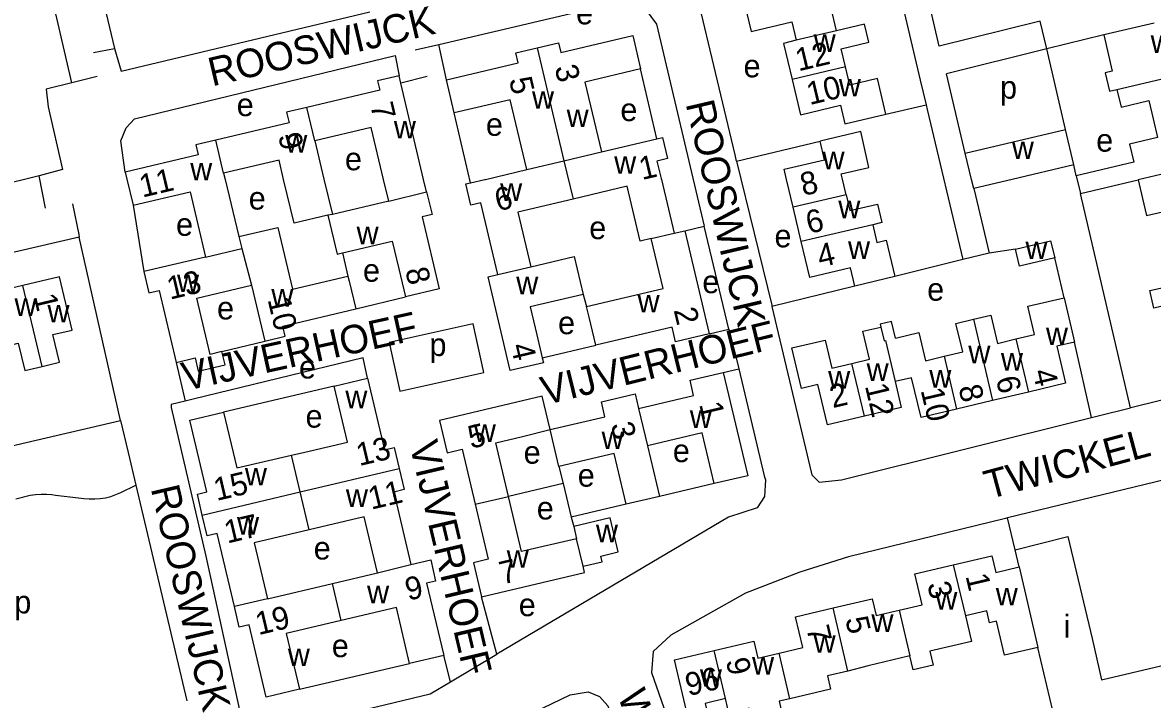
# Model space of a CAD drawing. Extents: x 157646 to 159241, y 379213 to 381217.
# Drawn here: x 158162.1 to 158360.1, y 380658.9 to 380777.5 of the extents above; entities that cross this region are included whole.
import ezdxf

# ---------------------------------------------------------------- set-up
doc = ezdxf.new("R2010")
doc.units = 0
for name, color, linetype in [('BLT_Basislijn', 7, 'Continuous'), ('BLT_Bebouwing', 7, 'Continuous'), ('BLT_Centroide', 7, 'Continuous'), ('BLT_Huisnummer', 7, 'Continuous'), ('BLT_Huisnummer_ tussenligend', 7, 'Continuous'), ('BLT_Onderverdeling_panden', 7, 'Continuous'), ('BLT_Straatnaam', 7, 'Continuous')]:
    doc.layers.add(name, color=color, linetype=linetype)

msp = doc.modelspace()

# ---------------------------------------------------------------- linework, layer by layer
at = {"layer": 'BLT_Basislijn'}
for p, q in [((158316.59, 380779.32), (158319.36, 380767.4)), ((158351.53, 380775.34), (158341.59, 380772.88)), ((158174.55, 380772.25), (158178.24, 380772.97)), ((158230.92, 380772.74), (158235.05, 380773.67)), ((158236.36, 380767.45), (158235.05, 380773.67)), ((158341.59, 380772.88), (158323.97, 380768.54)), ((158344.81, 380758.77), (158341.59, 380772.88)), ((158273.22, 380757.15), (158270.38, 380769.39)), ((158327.27, 380754.62), (158323.97, 380768.54)), ((158175.2, 380768.03), (158170.71, 380766.93)), ((158232.99, 380768.03), (158228.38, 380766.87)), ((158319.36, 380767.4), (158320.4, 380763.12)), ((158313.37, 380761.48), (158320.4, 380763.12)), ((158240.57, 380749.4), (158237.73, 380761.67)), ((158287.22, 380753.19), (158301.83, 380756.71)), ((158346.72, 380750.66), (158346.28, 380752.55)), ((158165, 380750.66), (158156.46, 380748.53)), ((158166.1, 380744.95), (158165, 380750.66)), ((158328.77, 380748.41), (158331.46, 380737.09)), ((158356.21, 380709.98), (158347.45, 380747.57)), ((158181.5, 380745.49), (158183.37, 380733.86)), ((158278.13, 380741.02), (158281.54, 380741.81)), ((158285.84, 380723.75), (158281.54, 380741.81)), ((158179.27, 380707.73), (158172.05, 380739.92)), ((158331.46, 380737.09), (158326.85, 380735.95)), ((158336.08, 380737.81), (158331.46, 380737.09)), ((158326.85, 380735.95), (158314.92, 380732.98)), ((158344.58, 380729.27), (158342.94, 380736.24)), ((158307.9, 380731.31), (158293.41, 380727.76)), ((158220.47, 380727.33), (158229.18, 380729.46)), ((158260.33, 380729.87), (158260.92, 380727.74)), ((158282.41, 380722.92), (158285.84, 380723.75)), ((158197.04, 380719.84), (158204.54, 380721.68)), ((158253.15, 380718.76), (158262.52, 380720.97)), ((158349.37, 380708.3), (158346.42, 380721.5)), ((158189.03, 380717.94), (158190.58, 380711.16)), ((158284.88, 380716.18), (158287.6, 380716.79)), ((158216.71, 380713.78), (158197.33, 380709.22)), ((158179.27, 380707.73), (158180.59, 380702.15)), ((158180.59, 380702.15), (158181.94, 380696.44)), ((158256.06, 380699.67), (158256.8, 380696.68)), ((158179.3, 380695.11), (158181.94, 380696.44)), ((158256.8, 380696.68), (158247.24, 380694.45)), ((158256.8, 380696.68), (158258.24, 380690.82)), ((158283.3, 380696.69), (158273.71, 380694.45)), ((158160.93, 380693.99), (158163.43, 380694.64)), ((158167.9, 380694.64), (158171.92, 380694.19)), ((158171.92, 380694.19), (158172.84, 380694.09)), ((158267.87, 380693.07), (158258.24, 380690.82)), ((158258.24, 380690.82), (158258.67, 380689.17)), ((158336.03, 380685.07), (158334.69, 380690.66)), ((158245.23, 380666.76), (158242.49, 380676.85)), ((158237.07, 380661.95), (158235.89, 380666.54)), ((158237.07, 380661.95), (158245.23, 380666.76)), ((158210.61, 380660.64), (158229.92, 380665.13))]:
    msp.add_line(p, q, dxfattribs=at)
for points in [[(158170.71, 380766.93), (158157.33, 380824.72), (158143.35, 380821.29)], [(158287.22, 380753.19), (158286.95, 380754.31), (158276.95, 380796.21)], [(158322.72, 380773.38), (158318.74, 380790.56), (158317.53, 380790.94), (158310.03, 380789.16)], [(158235.05, 380773.67), (158264.14, 380780.52), (158268.46, 380780.84), (158270.28, 380780.5), (158271.2, 380779.95), (158273.15, 380777.26), (158281.54, 380741.81)], [(158176.77, 380779.09), (158178.24, 380772.97)], [(158178.24, 380772.97), (158179.37, 380768.98), (158222.97, 380779.39)], [(158341.59, 380772.88), (158340.39, 380777.74), (158322.72, 380773.38)], [(158180.11, 380751.3), (158179.33, 380756.79), (158180.24, 380759.03), (158181.71, 380760.64), (158227.39, 380771.72), (158228.07, 380768.18)], [(158170.71, 380766.93), (158166.24, 380765.83), (158166.58, 380762.76), (158169.09, 380751.74), (158165, 380750.66)], [(158320.4, 380763.12), (158320.6, 380762.29), (158326.85, 380735.95)], [(158287.22, 380753.19), (158293.36, 380727.96), (158293.41, 380727.76)], [(158170.84, 380745.75), (158171.95, 380740.37), (158172.05, 380739.92)], [(158172.05, 380739.92), (158132.97, 380730.81), (158132.92, 380729.89), (158135.23, 380719.77)], [(158293.41, 380727.76), (158300.42, 380698.25), (158301.7, 380696.94), (158305.6, 380697.36), (158349.37, 380708.3)], [(158241.04, 380724.68), (158226.31, 380721.42), (158228.19, 380712.92), (158242.92, 380716.18), (158241.04, 380724.68)], [(158285.84, 380723.75), (158287.58, 380716.89), (158287.6, 380716.79)], [(158388.71, 380719.25), (158387.04, 380717.55), (158356.52, 380710.05), (158356.21, 380709.98)], [(158222.55, 380715.16), (158221.78, 380718.74), (158191.97, 380711.48), (158190.58, 380711.16)], [(158287.6, 380716.79), (158292.04, 380698.06), (158292.26, 380697.35), (158292.11, 380694.4), (158290.81, 380692.46), (158285.78, 380690.8), (158245.23, 380666.76)], [(158190.58, 380711.16), (158188.15, 380710.58), (158188.12, 380710.02), (158194.21, 380683.94), (158200.09, 380656.96), (158200.56, 380655.7), (158202.03, 380653.89), (158203.87, 380653.16), (158205.21, 380653.16), (158214.6, 380655.3), (158233.53, 380659.84), (158237.07, 380661.95)], [(158349.37, 380708.3), (158350.34, 380708.54), (158356.21, 380709.98)], [(158140.24, 380698.65), (158140.88, 380698.8), (158179.27, 380707.73)], [(158392.15, 380700.09), (158389.9, 380703.01), (158386.52, 380703.27), (158334.69, 380690.66)], [(158172.84, 380694.09), (158173.79, 380694), (158174.74, 380693.99), (158175.69, 380694.06), (158176.63, 380694.21), (158177.56, 380694.44), (158178.46, 380694.75), (158179.3, 380695.11)], [(158181.94, 380696.44), (158190.9, 380658.59)], [(158163.43, 380694.64), (158164.38, 380694.79), (158165.34, 380694.86), (158166.3, 380694.85), (158167.26, 380694.75), (158167.9, 380694.64)], [(158334.69, 380690.66), (158334.32, 380690.56), (158306.8, 380683.88), (158298.28, 380681.17), (158288.74, 380677.5), (158275.69, 380670.09), (158272.57, 380667.25), (158272.32, 380663.58), (158281.74, 380636.45), (158287.85, 380610.84), (158289.05, 380609.24)], [(158181.13, 380636.75), (158239.35, 380650.66), (158258.03, 380659.68), (158261.21, 380660.16), (158263.18, 380659.36), (158264.65, 380657.71), (158273.4, 380632.41), (158278.36, 380611.6), (158277.92, 380608.61), (158276.33, 380607.24), (158272.8, 380606.31), (158209.74, 380591.54), (158208.41, 380590.08)]]:
    msp.add_lwpolyline(points, dxfattribs=at)
at = {"layer": 'BLT_Bebouwing'}
for p, q in [((158360.36, 380777.43), (158351.53, 380775.34)), ((158228.38, 380766.87), (158228.07, 380768.18)), ((158237.73, 380761.67), (158236.36, 380767.45)), ((158296.92, 380767.52), (158298.38, 380761.35)), ((158346.28, 380752.55), (158344.81, 380758.77)), ((158263.52, 380754.85), (158273.22, 380757.15)), ((158346.72, 380750.66), (158347.45, 380747.57)), ((158347.45, 380747.57), (158357.54, 380749.95)), ((158226.27, 380746.22), (158216.4, 380743.88)), ((158298.55, 380739.15), (158297.12, 380745.15)), ((158216.4, 380743.88), (158215.6, 380743.72)), ((158276.3, 380740.59), (158278.13, 380741.02)), ((158278.13, 380741.02), (158282.41, 380722.92)), ((158200.01, 380739.98), (158200.54, 380737.92)), ((158200.54, 380737.92), (158202.22, 380731.47)), ((158218.15, 380737.15), (158219.11, 380733.08)), ((158194.15, 380736.41), (158183.37, 380733.86)), ((158314.92, 380732.98), (158307.9, 380731.31)), ((158162.14, 380731.41), (158155.86, 380729.9)), ((158202.22, 380731.47), (158204.54, 380721.68)), ((158344.58, 380729.27), (158346.42, 380721.5)), ((158216.71, 380713.78), (158222.55, 380715.16)), ((158317.88, 380715.25), (158314.98, 380714.57)), ((158332.05, 380711.25), (158325.75, 380709.76)), ((158338.36, 380712.74), (158332.05, 380711.25)), ((158256.06, 380699.67), (158254.54, 380706.15)), ((158271.61, 380703.33), (158273.71, 380694.45)), ((158273.71, 380694.45), (158267.87, 380693.07)), ((158336.73, 380682.08), (158336.03, 380685.07)), ((158216.42, 380679.19), (158224.27, 380681.04)), ((158205, 380676.49), (158216.42, 380679.19)), ((158235.89, 380666.54), (158229.92, 380665.13))]:
    msp.add_line(p, q, dxfattribs=at)
for points in [[(158304.72, 380776.07), (158303.3, 380782.1), (158298.39, 380780.93), (158297.65, 380784.06)], [(158288.38, 380781.86), (158289.78, 380775.93), (158296.9, 380777.62), (158297.66, 380774.4)], [(158306.28, 380769.74), (158305.53, 380772.92), (158310.36, 380774.06), (158309.61, 380777.23), (158304.72, 380776.07)], [(158252.28, 380773.06), (158256.01, 380773.95), (158256.41, 380772.25), (158269, 380775.24), (158270.38, 380769.39)], [(158297.66, 380774.4), (158295.41, 380773.87), (158296.92, 380767.52)], [(158351.53, 380775.34), (158353.03, 380768.99), (158351.81, 380768.7), (158352.57, 380765.49), (158353.83, 380765.79)], [(158236.36, 380767.45), (158248.96, 380770.44), (158248.55, 380772.18), (158252.28, 380773.06)], [(158270.38, 380769.39), (158260.63, 380767.07), (158263.52, 380754.85)], [(158313.37, 380761.48), (158311.9, 380767.71), (158307.03, 380766.56), (158306.28, 380769.74)], [(158228.07, 380768.18), (158224.32, 380767.29), (158224.7, 380765.68), (158211.93, 380762.65)], [(158232.9, 380747.84), (158232.38, 380750), (158228.38, 380766.87)], [(158353.83, 380765.79), (158354.56, 380762.69), (158359.44, 380763.85), (158360.21, 380760.61)], [(158211.93, 380762.65), (158208.36, 380761.8), (158208.8, 380759.96), (158195.94, 380756.91)], [(158250.44, 380751.74), (158247.53, 380763.99), (158237.73, 380761.67)], [(158298.38, 380761.35), (158305.43, 380763.02), (158306.2, 380759.78), (158313.37, 380761.48)], [(158360.21, 380760.61), (158360.97, 380757.38), (158356.06, 380756.22), (158356.81, 380753.04), (158346.72, 380750.66)], [(158226.27, 380746.22), (158225.34, 380750.01), (158223.18, 380759.12), (158213.31, 380756.78)], [(158306.4, 380747.3), (158305.75, 380750.07), (158305.54, 380750.98), (158310.4, 380752.13), (158308.98, 380758.4), (158301.83, 380756.71)], [(158327.27, 380754.62), (158344.81, 380758.77)], [(158195.94, 380756.91), (158192.48, 380756.09), (158192.9, 380754.33), (158180.11, 380751.3)], [(158213.31, 380756.78), (158214.91, 380750.05), (158216.4, 380743.88)], [(158273.22, 380757.15), (158274.22, 380757.38), (158275.1, 380753.68), (158273.26, 380753.24), (158273.98, 380750.2), (158274.03, 380750), (158276.3, 380740.59)], [(158297.12, 380745.15), (158295.97, 380750), (158295.54, 380751.8), (158302.59, 380753.47), (158301.83, 380756.71)], [(158328.77, 380748.41), (158328.36, 380750), (158327.27, 380754.62)], [(158215.6, 380743.72), (158209.7, 380742.32), (158207.85, 380750), (158207.04, 380753.4), (158197.32, 380751.1)], [(158346.28, 380752.55), (158335.5, 380750), (158328.77, 380748.41)], [(158180.11, 380751.3), (158180.4, 380750.08), (158181.5, 380745.49)], [(158197.32, 380751.1), (158197.58, 380750), (158200.01, 380739.98)], [(158240.57, 380749.4), (158243.12, 380750), (158243.22, 380750.03), (158250.44, 380751.74)], [(158245.38, 380733.34), (158242.41, 380745.92), (158240.67, 380745.5), (158239.79, 380749.22), (158240.57, 380749.4)], [(158272.26, 380739.64), (158270.33, 380739.18), (158268.06, 380748.81), (158258.56, 380746.57)], [(158357.54, 380749.95), (158358.31, 380746.68), (158359.02, 380743.68), (158363.86, 380744.82), (158364.61, 380741.62)], [(158181.5, 380745.49), (158191.45, 380747.84), (158194.15, 380736.41)], [(158232.9, 380747.84), (158233.87, 380743.88), (158232.1, 380743.46), (158235.08, 380730.85), (158229.18, 380729.46)], [(158258.56, 380746.57), (158248.9, 380744.29), (158251.17, 380734.71)], [(158306.4, 380747.3), (158307.04, 380744.54), (158311.9, 380745.7), (158312.67, 380742.46), (158311.05, 380742.08)], [(158215.6, 380743.72), (158217.21, 380736.93), (158218.15, 380737.15)], [(158200.01, 380739.98), (158206.84, 380741.59), (158209.39, 380730.78), (158219.11, 380733.08)], [(158311.05, 380742.08), (158311.8, 380738.95), (158313.41, 380739.34), (158314.92, 380732.98)], [(158218.15, 380737.15), (158226.87, 380739.21), (158228.03, 380734.32), (158229.18, 380729.46)], [(158260.92, 380727.74), (158274.32, 380730.9), (158272.26, 380739.64)], [(158307.9, 380731.31), (158307.15, 380734.5), (158300.06, 380732.81), (158298.55, 380739.15)], [(158336.08, 380737.81), (158342.23, 380739.27), (158342.94, 380736.24)], [(158342.94, 380736.24), (158336.79, 380734.8), (158336.08, 380737.81)], [(158251.17, 380734.71), (158258.77, 380736.51), (158260.33, 380729.87)], [(158165.54, 380717.22), (158168.59, 380717.95), (158167.43, 380722.8), (158170.81, 380723.61), (158168.57, 380732.95), (158162.14, 380731.41)], [(158183.37, 380733.86), (158184.25, 380730.11), (158186.05, 380730.53), (158189.03, 380717.94)], [(158219.11, 380733.08), (158219.32, 380732.19), (158220.47, 380727.33)], [(158253.15, 380718.76), (158253.35, 380717.89), (158247.54, 380716.52), (158243.66, 380732.93), (158245.38, 380733.34)], [(158197.04, 380719.84), (158194.98, 380719.34), (158192.65, 380729.21), (158202.22, 380731.47)], [(158364.52, 380725.01), (158363.76, 380728.25), (158360.33, 380727.44), (158359.6, 380730.53), (158362, 380731.09)], [(158260.33, 380729.87), (158251.04, 380727.67), (158252.2, 380722.76), (158253.15, 380718.76)], [(158336.16, 380722.04), (158339.41, 380722.81), (158338.24, 380727.77), (158344.58, 380729.27)], [(158204.54, 380721.68), (158208.1, 380722.52), (158207.68, 380724.3), (158220.47, 380727.33)], [(158262.52, 380720.97), (158261.37, 380725.84), (158260.92, 380727.74)], [(158315.06, 380722.19), (158314.37, 380725.1), (158312.38, 380724.63), (158312.5, 380724.14)], [(158323.56, 380719.01), (158326.82, 380719.78), (158325.64, 380724.77), (158328.69, 380725.49)], [(158328.69, 380725.49), (158331.74, 380726.21), (158332.9, 380721.27), (158336.16, 380722.04)], [(158282.41, 380722.92), (158276.52, 380721.53), (158275.91, 380724.14), (158262.52, 380720.97)], [(158307.41, 380717.76), (158310.49, 380718.49), (158309.33, 380723.39), (158312.5, 380724.14)], [(158315.06, 380722.19), (158319.15, 380723.15), (158320.31, 380718.24), (158323.56, 380719.01)], [(158158.11, 380720.52), (158161.34, 380721.29), (158162.5, 380716.49), (158165.54, 380717.22)], [(158309.59, 380708.52), (158303.14, 380707), (158301.46, 380714.09), (158298.59, 380713.35), (158296.91, 380720.49), (158302.74, 380721.86), (158303.9, 380716.93), (158307.41, 380717.76)], [(158346.42, 380721.5), (158343.32, 380720.77), (158344.86, 380714.27), (158338.36, 380712.74)], [(158189.03, 380717.94), (158192.32, 380718.72), (158192.87, 380716.38), (158197.59, 380717.5), (158197.04, 380719.84)], [(158222.55, 380715.16), (158225.52, 380702.59), (158227.21, 380702.99), (158228.08, 380699.33)], [(158270.02, 380709.87), (158279.68, 380712.15), (158279.05, 380714.81), (158284.88, 380716.18)], [(158284.88, 380716.18), (158289.16, 380698.08), (158283.3, 380696.69)], [(158325.75, 380709.76), (158319.53, 380708.29), (158317.88, 380715.25)], [(158209.23, 380701.68), (158211.57, 380702.22), (158219.02, 380703.98), (158216.71, 380713.78)], [(158314.98, 380714.57), (158316.04, 380710.04), (158309.59, 380708.52)], [(158254.54, 380706.15), (158253.15, 380712.01), (158235.15, 380707.76), (158236.49, 380702.08), (158239.13, 380702.71), (158241.41, 380693.07)], [(158254.54, 380706.15), (158264.15, 380708.42), (158263.53, 380711.05), (158269.41, 380712.43), (158270.02, 380709.87)], [(158193.6, 380691.18), (158192.73, 380694.86), (158194.37, 380695.24), (158191.39, 380707.82), (158197.33, 380709.22)], [(158197.33, 380709.22), (158199.64, 380699.43), (158209.23, 380701.68)], [(158247.24, 380694.45), (158245.02, 380703.85), (158249.68, 380704.95), (158254.54, 380706.15)], [(158283.3, 380696.69), (158281.2, 380705.6), (158271.61, 380703.33)], [(158267.87, 380693.07), (158265.77, 380701.97), (158256.06, 380699.67)], [(158228.08, 380699.33), (158228.96, 380695.63), (158227.13, 380695.19), (158230.13, 380682.49)], [(158241.41, 380693.07), (158243.69, 380683.43), (158241.09, 380682.81), (158242.49, 380676.85)], [(158259.17, 380687.03), (158249.53, 380684.76), (158247.24, 380694.45)], [(158199.22, 380675.12), (158196.19, 380687.92), (158194.47, 380687.51), (158193.6, 380691.18)], [(158224.27, 380681.04), (158221.95, 380690.89), (158212.31, 380688.61)], [(158260.32, 380682.21), (158263.65, 380682.99), (158263.42, 380683.98), (158266.45, 380684.7), (158265.04, 380690.67), (158258.67, 380689.17)], [(158258.67, 380689.17), (158259.17, 380687.03)], [(158212.31, 380688.61), (158202.68, 380686.33), (158205, 380676.49)], [(158336.03, 380685.07), (158345.27, 380687.41), (158349.48, 380669.51), (158351.17, 380662.3), (158371.95, 380667.18), (158369.16, 380679.07), (158377.01, 380680.91)], [(158230.13, 380682.49), (158233.61, 380683.31), (158234.48, 380679.61), (158232.89, 380679.23), (158235.89, 380666.54)], [(158325.18, 380682.45), (158331.93, 380684.03), (158332.61, 380681.11), (158336.73, 380682.08)], [(158242.49, 380676.85), (158260.57, 380681.12), (158260.32, 380682.21)], [(158315.67, 380674.5), (158319.71, 380675.45), (158318.44, 380680.86), (158325.18, 380682.45)], [(158304.1, 380674.89), (158310.95, 380676.49), (158311.64, 380673.55), (158315.67, 380674.5)], [(158210.61, 380660.64), (158204.81, 380659.27), (158201.82, 380671.94), (158200.07, 380671.53), (158199.22, 380675.12)], [(158229.92, 380665.13), (158227.6, 380674.98), (158217.95, 380672.7)], [(158294.68, 380666.97), (158298.79, 380667.93), (158297.52, 380673.34), (158304.1, 380674.89)], [(158327.29, 380673.5), (158328.34, 380669), (158321.08, 380667.3), (158321.65, 380664.85), (158318.14, 380664.02), (158317.56, 380666.47)], [(158339.99, 380667.96), (158334.14, 380666.59), (158332.74, 380672.55), (158331.52, 380672.26), (158331.03, 380674.38), (158327.29, 380673.5)], [(158217.95, 380672.7), (158208.3, 380670.42), (158210.61, 380660.64)], [(158285.27, 380659), (158281.7, 380658.16), (158282.29, 380655.66), (158278.88, 380654.86), (158276.31, 380665.8), (158283.28, 380667.44)], [(158283.28, 380667.44), (158290.21, 380669.06), (158290.91, 380666.09), (158294.68, 380666.97)], [(158343.74, 380651.99), (158342.6, 380656.85), (158339.99, 380667.96)], [(158317.56, 380666.47), (158310.25, 380664.75), (158306.71, 380663.8)], [(158306.71, 380663.8), (158303.13, 380663), (158303.68, 380660.65), (158296.55, 380658.98)], [(158296.55, 380658.98), (158294.66, 380658.54), (158295.13, 380656.52), (158294.9, 380655.12), (158294.05, 380654.22), (158292.32, 380653.81), (158290.93, 380654.04), (158289.99, 380654.92), (158289.43, 380657.31), (158285.86, 380656.47), (158285.27, 380659)]]:
    msp.add_lwpolyline(points, dxfattribs=at)
at = {"layer": 'BLT_Onderverdeling_panden'}
for p, q in [((158304.72, 380776.07), (158297.66, 380774.4)), ((158252.28, 380773.06), (158256.96, 380753.29)), ((158306.28, 380769.74), (158296.92, 380767.52)), ((158353.83, 380765.79), (158367.95, 380769.13)), ((158213.31, 380756.78), (158211.93, 380762.65)), ((158197.32, 380751.1), (158195.94, 380756.91)), ((158256.96, 380753.29), (158263.52, 380754.85)), ((158250.44, 380751.74), (158256.96, 380753.29)), ((158256.96, 380753.29), (158258.56, 380746.57)), ((158364.64, 380751.63), (158357.54, 380749.95)), ((158226.27, 380746.22), (158232.9, 380747.84)), ((158306.4, 380747.3), (158297.12, 380745.15)), ((158272.26, 380739.64), (158276.3, 380740.59)), ((158311.05, 380742.08), (158298.55, 380739.15)), ((158194.15, 380736.41), (158200.54, 380737.92)), ((158245.38, 380733.34), (158251.17, 380734.71)), ((158165.54, 380717.22), (158162.14, 380731.41)), ((158328.69, 380725.49), (158332.05, 380711.25)), ((158336.16, 380722.04), (158338.36, 380712.74)), ((158323.56, 380719.01), (158325.75, 380709.76)), ((158309.59, 380708.52), (158307.41, 380717.76)), ((158270.02, 380709.87), (158271.61, 380703.33)), ((158210.75, 380695.24), (158209.23, 380701.68)), ((158210.75, 380695.24), (158228.08, 380699.33)), ((158193.6, 380691.18), (158210.75, 380695.24)), ((158212.31, 380688.61), (158210.75, 380695.24)), ((158241.41, 380693.07), (158247.24, 380694.45)), ((158260.32, 380682.21), (158259.17, 380687.03)), ((158224.27, 380681.04), (158230.13, 380682.49)), ((158325.18, 380682.45), (158327.29, 380673.5)), ((158336.73, 380682.08), (158339.99, 380667.96)), ((158217.95, 380672.7), (158216.42, 380679.19)), ((158205, 380676.49), (158199.22, 380675.12)), ((158306.71, 380663.8), (158304.1, 380674.89)), ((158315.67, 380674.5), (158317.56, 380666.47)), ((158285.27, 380659), (158283.28, 380667.44)), ((158296.55, 380658.98), (158294.68, 380666.97))]:
    msp.add_line(p, q, dxfattribs=at)
msp.add_lwpolyline([(158312.5, 380724.14), (158313.07, 380721.72), (158313.27, 380721.77), (158314.98, 380714.57)], dxfattribs=at)

# ---------------------------------------------------------------- texts
at = {"layer": 'BLT_Centroide'}
for s, p in [('e', (158259.09, 380777.2)), ('w', (158300.71, 380772.38)), ('w', (158359.76, 380772.19)), ('e', (158288.43, 380767.91)), ('w', (158305.12, 380764.56)), ('p', (158333.37, 380764.17)), ('w', (158251.36, 380762.41)), ('e', (158199.63, 380761.11)), ('e', (158266.85, 380760.24)), ('e', (158243.29, 380757.66)), ('w', (158257.43, 380759.2)), ('w', (158227.16, 380757.19)), ('w', (158208.13, 380754.72)), ('w', (158335.44, 380753.59)), ('e', (158350.21, 380754.88)), ('e', (158218.59, 380751.62)), ('w', (158302.26, 380751.78)), ('w', (158191.48, 380749.85)), ('w', (158265.76, 380751)), ('w', (158245.78, 380746.26)), ('e', (158201.73, 380744.73)), ('w', (158305.03, 380743.22)), ('e', (158189, 380740.13)), ('e', (158261.39, 380739.55)), ('w', (158220.63, 380738.66)), ('e', (158293.85, 380738.11)), ('w', (158306.73, 380736.09)), ('w', (158337.82, 380736.05)), ('e', (158221.75, 380732.08)), ('w', (158189.17, 380730.26)), ('w', (158248.6, 380729.87)), ('e', (158281.21, 380730.07)), ('w', (158205.69, 380727.73)), ('e', (158320.6, 380728.75)), ('w', (158160.7, 380726.09)), ('w', (158269.86, 380726.7)), ('w', (158166.47, 380724.94)), ('e', (158196.18, 380725.47)), ('e', (158255.93, 380722.88)), ('w', (158341.41, 380720.98)), ('p', (158233.4, 380719.06)), ('w', (158327.81, 380717.77)), ('w', (158333.52, 380716.5)), ('e', (158210.55, 380715.12)), ('w', (158309.99, 380714.7)), ('w', (158303.25, 380713.34)), ('w', (158320.97, 380713.52)), ('w', (158218.66, 380709.91)), ('e', (158211.69, 380706.5)), ('w', (158279.02, 380706.44)), ('w', (158241.17, 380704)), ('w', (158263.55, 380702.75)), ('e', (158249.9, 380700.18)), ('e', (158276.04, 380700.46)), ('w', (158201.06, 380696.36)), ('e', (158259.38, 380696.15)), ('w', (158218.76, 380692.6)), ('e', (158252.2, 380690.4)), ('w', (158199.68, 380687.74)), ('w', (158262.56, 380686.42)), ('e', (158213.12, 380683.38)), ('w', (158246.93, 380681.94)), ('w', (158222.47, 380675.7)), ('w', (158322.02, 380674.59)), ('w', (158332.62, 380675.34)), ('p', (158160.66, 380673.94)), ('e', (158249.04, 380673.45)), ('w', (158310.83, 380670.67)), ('i', (158344.52, 380669.69)), ('e', (158216.29, 380666.26)), ('w', (158300.7, 380667.03)), ('w', (158208.58, 380664.69)), ('w', (158289.92, 380663.22)), ('w', (158280.78, 380661.08))]:
    msp.add_text(s, height=4, dxfattribs=at).set_placement(p)
at = {"layer": 'BLT_Huisnummer'}
for s, rotation, p in [('12', 13.3877, (158298.05, 380768.95)), ('3', 283.335, (158255.31, 380769.66)), ('5', 283.3327, (158247.31, 380767.53)), ('10', 13.3877, (158300.01, 380763.04)), ('7', 283.3336, (158222.99, 380763.06)), ('9', 283.5524, (158206.85, 380757.73)), ('1', 13.2964, (158270.64, 380749.89)), ('11', 13.2925, (158183.09, 380746.82)), ('8', 13.3877, (158298.89, 380747.11)), ('6', 13.296, (158245.36, 380744.4)), ('4', 13.3945, (158301.85, 380734.54)), ('8', 283.2969, (158229.12, 380734.15)), ('13', 13.2996, (158187.93, 380728.92)), ('1', 283.4984, (158164.03, 380729.54)), ('10', 283.2931, (158205.02, 380728.97)), ('2', 283.2917, (158276.17, 380727.12)), ('4', 283.293, (158247.6, 380720.86)), ('4', 283.2968, (158339.05, 380716.34)), ('2', 13.293, (158304.05, 380709.91)), ('12', 283.2955, (158309.67, 380713.84)), ('10', 283.2905, (158319.44, 380713.06)), ('1', 283.2982, (158280.64, 380710.6)), ('5', 13.1837, (158240.66, 380702.78)), ('3', 283.2944, (158265.12, 380707.03)), ('13', 13.2906, (158221.1, 380699.75)), ('15', 13.1601, (158196.1, 380693.64)), ('11', 13.2952, (158223.19, 380692.1)), ('17', 13.2952, (158197.96, 380686.17)), ('7', 13.294, (158246.16, 380678.98)), ('9', 13.2999, (158229.66, 380676.14)), ('3', 283.2264, (158320.59, 380679.07)), ('1', 283.2163, (158327.3, 380680.5)), ('19', 13.2946, (158203.43, 380670.11)), ('5', 283.2264, (158306.22, 380672.95)), ('7', 283.2252, (158299.4, 380671.37)), ('9', 283.2292, (158285.29, 380665.69)), ('96', 13.2178, (158278.74, 380659.42))]:
    msp.add_text(s, height=4, rotation=rotation, dxfattribs=at).set_placement(p)
at = {"layer": 'BLT_Huisnummer_ tussenligend'}
for s, rotation, p in [('6', 13.3945, (158299.88, 380740.45)), ('6', 283.2968, (158332.61, 380715.09)), ('8', 283.2905, (158326.06, 380713.57))]:
    msp.add_text(s, height=4, rotation=rotation, dxfattribs=at).set_placement(p)
at = {"layer": 'BLT_Straatnaam'}
for s, rotation, p in [('ROOSWIJCK', 13.2774, (158195.31, 380766.31)), ('ROOSWIJCK', 283.1965, (158278.25, 380763.3)), ('VIJVERHOEF', 12.4701, (158190.64, 380712.93)), ('VIJVERHOEF', 13.8837, (158253.65, 380710.42)), ('TWICKEL', 15.0322, (158331.38, 380693.93)), ('VIJVERHOEF', 283.2933, (158229.87, 380703.57)), ('ROOSWIJCK', 283.1446, (158184.55, 380695.84)), ('WARMELO', 289.08, (158266.33, 380659.6))]:
    msp.add_text(s, height=5, rotation=rotation, dxfattribs=at).set_placement(p)

doc.saveas('drawing.dxf')
